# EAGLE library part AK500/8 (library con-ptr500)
CONNECTOR
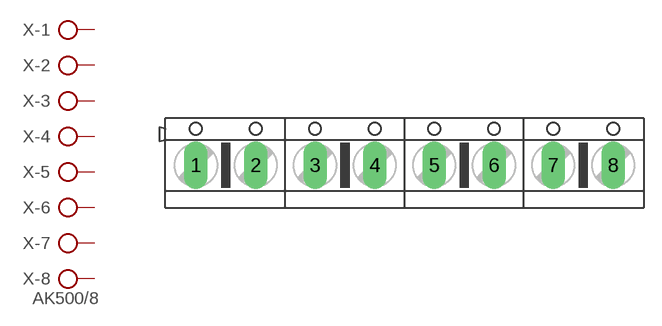
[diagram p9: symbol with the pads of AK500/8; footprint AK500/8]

Designator prefix X; gates -1=KL -2=KL -3=KL -4=KL -5=KL -6=KL -7=KL -8=KLV

## AK500/8 (OC_FARNELL: unknown; OC_NEWARK: unknown)  [AK500/8]
1  -1:KL  pas
2  -2:KL  pas
3  -3:KL  pas
4  -4:KL  pas
5  -5:KL  pas
6  -6:KL  pas
7  -7:KL  pas
8  -8:KL  pas

## Footprint AK500/8 (pad centres in mm)
CONNECTOR
drill 1.321 long: 1 -17.526,0; 2 -12.497,0; 3 -7.518,0; 4 -2.489,0; 5 2.489,0; 6 7.518,0; 7 12.497,0; 8 17.526,0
